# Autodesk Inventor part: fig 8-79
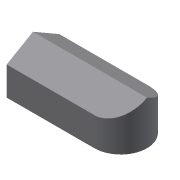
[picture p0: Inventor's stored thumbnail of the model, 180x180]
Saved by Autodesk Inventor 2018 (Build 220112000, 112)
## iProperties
Created: 2011-07
Part Number: fig 8-79
Material: Generic
Document SubType Name: Modeling
Designer: CadCim
Density: 1 g/cm^3
Appearance: Default
Author: CadCim
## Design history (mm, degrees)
sketch "Sketch1"
  geometry: L1 (-16, 5)-(-16, -7); L2 (-16, -7)-(4, -7); L3 (4, 5)-(-16, 5); A1 r 6 centre (4, -1) between (4, -7) and (4, 5); 1 further point
  constraints: 6 end point, 2 point on circle, 2 tangent, 1 centre point, 1 parallel, 1 perpendicular, 1 vertical
extrude "Extrusion1" new body sketch "Sketch1" distance "d0" = 10; taper "d1" = 0 deg
sketch "Sketch2"
  geometry: L1 (-16, -1)-(10, -1); 1 further point
  constraints: 2 end point, 1 horizontal
feature "FaceDraft1" sketch "Sketch2" dims angle "d2" = 30 deg
body "Solid1"
